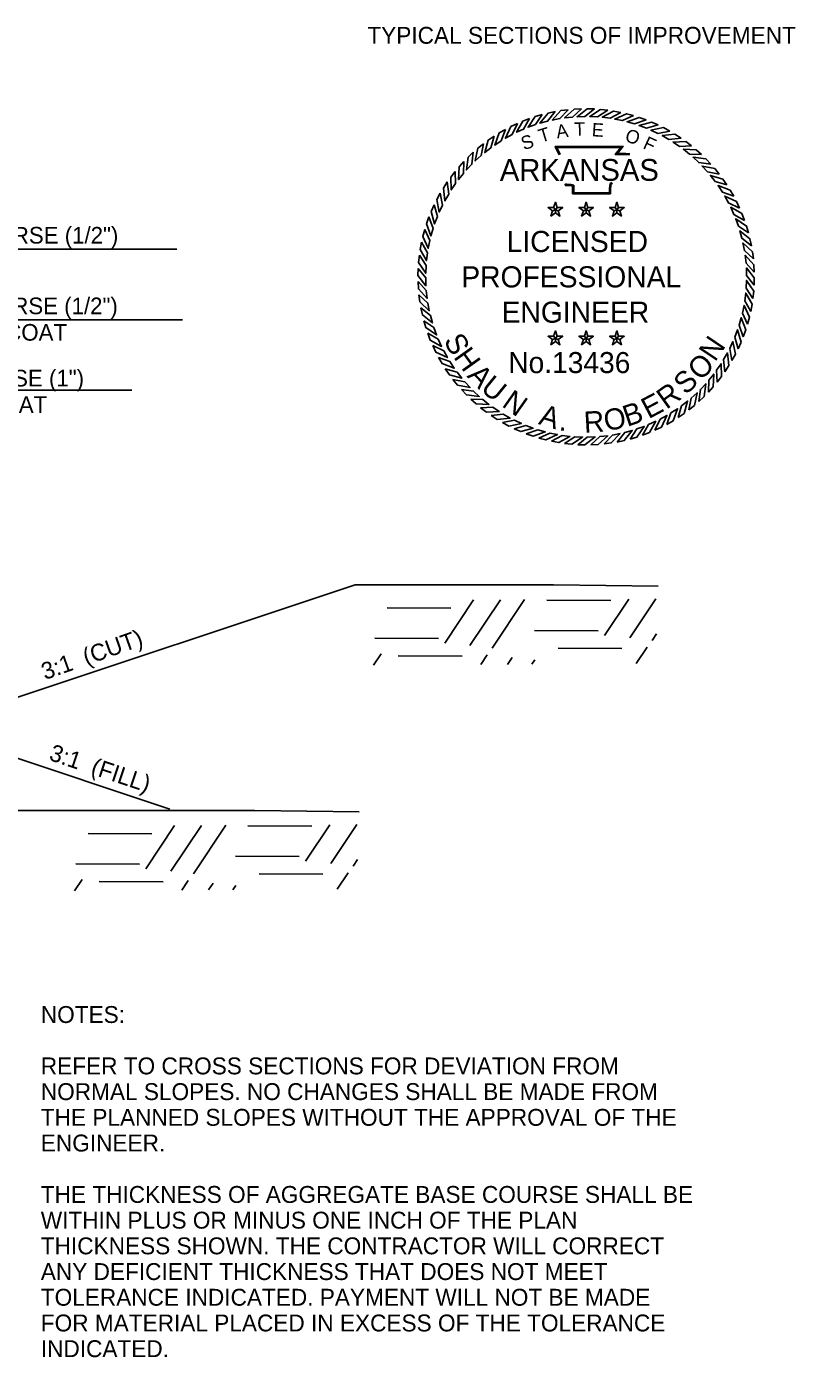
# Model space of a CAD drawing. Extents: x 1398183 to 1398373, y 1967240 to 1968889.
# Drawn here: x 1398309.13 to 1398336.4, y 1967288.58 to 1967335.82 of the extents above; entities that cross this region are included whole.
import ezdxf

# ---------------------------------------------------------------- set-up
doc = ezdxf.new("R2010")
doc.units = 0
for name, color, linetype in [('1', 7, 'Continuous'), ('19', 7, 'Continuous'), ('20', 7, 'Continuous'), ('42', 7, 'Continuous'), ('9', 7, 'Continuous'), ('G-ANNO-SYMB', 7, 'Continuous')]:
    doc.layers.add(name, color=color, linetype=linetype)

msp = doc.modelspace()

# ---------------------------------------------------------------- linework, layer by layer
at = {"layer": '19'}
for q in [(1398320.78, 1967316.011), (1398314.215, 1967308.042)]:
    msp.add_line((1398305.544, 1967310.932), q, dxfattribs=at)
at = {"layer": '20'}
for p, q in [((1398286.544, 1967327.92), (1398314.465, 1967327.92)), ((1398286.544, 1967325.42), (1398314.665, 1967325.42)), ((1398286.544, 1967322.92), (1398312.868, 1967322.92))]:
    msp.add_line(p, q, dxfattribs=at)
at = {"layer": '42'}
for points in [[(1398320.78, 1967316.011), (1398327.818, 1967316.011), (1398331.534, 1967315.96)], [(1398307.157, 1967308.001), (1398317.211, 1967308.001), (1398320.926, 1967307.951)]]:
    msp.add_lwpolyline(points, dxfattribs=at)
at = {"layer": '9'}
for p, q in [((1398324.18, 1967315.183), (1398321.918, 1967315.189)), ((1398324.987, 1967315.473), (1398323.964, 1967313.939)), ((1398325.939, 1967315.478), (1398324.854, 1967313.851)), ((1398326.799, 1967315.483), (1398325.652, 1967313.763)), ((1398329.851, 1967315.456), (1398327.589, 1967315.462)), ((1398330.497, 1967315.504), (1398329.636, 1967314.212)), ((1398331.45, 1967315.509), (1398330.526, 1967314.124)), ((1398323.741, 1967314.105), (1398321.479, 1967314.111)), ((1398329.412, 1967314.378), (1398327.15, 1967314.383)), ((1398331.478, 1967314.266), (1398331.324, 1967314.036)), ((1398330.25, 1967313.752), (1398327.988, 1967313.757)), ((1398331.14, 1967313.794), (1398330.752, 1967313.211)), ((1398321.704, 1967313.555), (1398321.44, 1967313.159)), ((1398324.578, 1967313.479), (1398322.316, 1967313.485)), ((1398325.468, 1967313.521), (1398325.241, 1967313.18)), ((1398326.358, 1967313.433), (1398326.193, 1967313.185)), ((1398327.156, 1967313.345), (1398327.053, 1967313.19)), ((1398319.89, 1967307.494), (1398319.028, 1967306.202)), ((1398320.842, 1967307.5), (1398319.919, 1967306.114)), ((1398313.572, 1967307.173), (1398311.31, 1967307.179)), ((1398314.379, 1967307.463), (1398313.357, 1967305.929)), ((1398315.332, 1967307.469), (1398314.247, 1967305.842)), ((1398316.192, 1967307.474), (1398315.045, 1967305.753)), ((1398319.244, 1967307.446), (1398316.982, 1967307.452)), ((1398313.133, 1967306.095), (1398310.871, 1967306.101)), ((1398318.805, 1967306.368), (1398316.543, 1967306.374)), ((1398320.87, 1967306.257), (1398320.717, 1967306.026)), ((1398319.643, 1967305.742), (1398317.381, 1967305.748)), ((1398320.533, 1967305.784), (1398320.144, 1967305.201)), ((1398311.097, 1967305.546), (1398310.833, 1967305.149)), ((1398313.971, 1967305.469), (1398311.709, 1967305.475)), ((1398314.861, 1967305.511), (1398314.634, 1967305.171)), ((1398315.751, 1967305.423), (1398315.586, 1967305.176)), ((1398316.549, 1967305.335), (1398316.446, 1967305.181))]:
    msp.add_line(p, q, dxfattribs=at)
at = {"layer": 'G-ANNO-SYMB'}
for points in [[(1398326.975, 1967332.56), (1398326.735, 1967332.469), (1398326.51, 1967332.071), (1398326.763, 1967332.185)], [(1398327.422, 1967332.7), (1398327.176, 1967332.628), (1398326.92, 1967332.249), (1398327.181, 1967332.343)], [(1398327.879, 1967332.805), (1398327.628, 1967332.752), (1398327.343, 1967332.394), (1398327.61, 1967332.467)], [(1398328.342, 1967332.873), (1398328.088, 1967332.84), (1398327.776, 1967332.506), (1398328.048, 1967332.558)], [(1398328.81, 1967332.905), (1398328.553, 1967332.892), (1398328.216, 1967332.583), (1398328.492, 1967332.614)], [(1398329.278, 1967332.9), (1398329.021, 1967332.907), (1398328.661, 1967332.626), (1398328.938, 1967332.634)], [(1398329.745, 1967332.858), (1398329.489, 1967332.886), (1398329.108, 1967332.633), (1398329.385, 1967332.62)], [(1398330.206, 1967332.78), (1398329.954, 1967332.827), (1398329.554, 1967332.606), (1398329.829, 1967332.571)], [(1398330.661, 1967332.666), (1398330.413, 1967332.733), (1398329.997, 1967332.543), (1398330.268, 1967332.487)], [(1398331.105, 1967332.516), (1398330.863, 1967332.602), (1398330.433, 1967332.446), (1398330.699, 1967332.369)], [(1398326.121, 1967332.177), (1398325.898, 1967332.05), (1398325.738, 1967331.621), (1398325.97, 1967331.774)], [(1398326.54, 1967332.386), (1398326.309, 1967332.276), (1398326.115, 1967331.861), (1398326.358, 1967331.995)], [(1398331.535, 1967332.332), (1398331.301, 1967332.437), (1398330.861, 1967332.315), (1398331.12, 1967332.217)], [(1398331.951, 1967332.115), (1398331.725, 1967332.238), (1398331.277, 1967332.151), (1398331.527, 1967332.033)], [(1398325.337, 1967331.666), (1398325.137, 1967331.505), (1398325.046, 1967331.057), (1398325.251, 1967331.243)], [(1398325.719, 1967331.937), (1398325.507, 1967331.792), (1398325.381, 1967331.353), (1398325.6, 1967331.523)], [(1398332.347, 1967331.866), (1398332.132, 1967332.006), (1398331.678, 1967331.955), (1398331.919, 1967331.817)], [(1398332.723, 1967331.587), (1398332.52, 1967331.743), (1398332.063, 1967331.727), (1398332.292, 1967331.572)], [(1398324.977, 1967331.365), (1398324.791, 1967331.189), (1398324.735, 1967330.735), (1398324.925, 1967330.937)], [(1398333.076, 1967331.279), (1398332.886, 1967331.451), (1398332.429, 1967331.471), (1398332.646, 1967331.298)], [(1398333.404, 1967330.944), (1398333.228, 1967331.13), (1398332.774, 1967331.186), (1398332.976, 1967330.997)], [(1398324.335, 1967330.685), (1398324.178, 1967330.481), (1398324.194, 1967330.025), (1398324.35, 1967330.254)], [(1398324.643, 1967331.038), (1398324.471, 1967330.847), (1398324.451, 1967330.391), (1398324.624, 1967330.607)], [(1398333.704, 1967330.585), (1398333.543, 1967330.784), (1398333.095, 1967330.875), (1398333.282, 1967330.671)], [(1398324.055, 1967330.309), (1398323.915, 1967330.094), (1398323.967, 1967329.639), (1398324.104, 1967329.88)], [(1398333.976, 1967330.203), (1398333.831, 1967330.414), (1398333.391, 1967330.54), (1398333.561, 1967330.321)], [(1398334.216, 1967329.801), (1398334.088, 1967330.023), (1398333.66, 1967330.183), (1398333.812, 1967329.952)], [(1398323.806, 1967329.912), (1398323.683, 1967329.687), (1398323.771, 1967329.238), (1398323.888, 1967329.489)], [(1398334.424, 1967329.381), (1398334.314, 1967329.613), (1398333.9, 1967329.806), (1398334.034, 1967329.563)], [(1398323.589, 1967329.497), (1398323.484, 1967329.263), (1398323.606, 1967328.822), (1398323.704, 1967329.081)], [(1398327.889, 1967329.317), (1398327.828, 1967329.401), (1398327.63, 1967329.401), (1398327.79, 1967329.285)], [(1398327.889, 1967329.317), (1398327.79, 1967329.285), (1398327.729, 1967329.096), (1398327.889, 1967329.213)], [(1398327.889, 1967329.317), (1398327.95, 1967329.401), (1398327.889, 1967329.59), (1398327.828, 1967329.401)], [(1398327.889, 1967329.317), (1398327.988, 1967329.285), (1398328.148, 1967329.401), (1398327.95, 1967329.401)], [(1398327.889, 1967329.317), (1398327.889, 1967329.213), (1398328.049, 1967329.096), (1398327.988, 1967329.285)], [(1398328.98, 1967329.317), (1398328.919, 1967329.401), (1398328.721, 1967329.401), (1398328.881, 1967329.285)], [(1398328.98, 1967329.317), (1398328.881, 1967329.285), (1398328.82, 1967329.096), (1398328.98, 1967329.213)], [(1398328.98, 1967329.317), (1398329.041, 1967329.401), (1398328.98, 1967329.59), (1398328.919, 1967329.401)], [(1398328.98, 1967329.317), (1398329.079, 1967329.285), (1398329.239, 1967329.401), (1398329.041, 1967329.401)], [(1398328.98, 1967329.317), (1398328.98, 1967329.213), (1398329.14, 1967329.096), (1398329.079, 1967329.285)], [(1398330.071, 1967329.317), (1398330.01, 1967329.401), (1398329.812, 1967329.401), (1398329.972, 1967329.285)], [(1398330.071, 1967329.317), (1398329.972, 1967329.285), (1398329.911, 1967329.096), (1398330.071, 1967329.213)], [(1398330.071, 1967329.317), (1398330.132, 1967329.401), (1398330.071, 1967329.59), (1398330.01, 1967329.401)], [(1398330.071, 1967329.317), (1398330.17, 1967329.285), (1398330.33, 1967329.401), (1398330.132, 1967329.401)], [(1398330.071, 1967329.317), (1398330.071, 1967329.213), (1398330.231, 1967329.096), (1398330.17, 1967329.285)], [(1398334.599, 1967328.946), (1398334.508, 1967329.186), (1398334.11, 1967329.411), (1398334.224, 1967329.159)], [(1398323.405, 1967329.066), (1398323.319, 1967328.824), (1398323.475, 1967328.395), (1398323.553, 1967328.661)], [(1398334.739, 1967328.499), (1398334.667, 1967328.745), (1398334.288, 1967329.001), (1398334.382, 1967328.74)], [(1398323.256, 1967328.622), (1398323.189, 1967328.374), (1398323.378, 1967327.958), (1398323.434, 1967328.23)], [(1398334.843, 1967328.043), (1398334.791, 1967328.294), (1398334.433, 1967328.578), (1398334.506, 1967328.311)], [(1398323.141, 1967328.168), (1398323.094, 1967327.916), (1398323.316, 1967327.516), (1398323.35, 1967327.791)], [(1398334.912, 1967327.579), (1398334.879, 1967327.834), (1398334.544, 1967328.146), (1398334.596, 1967327.873)], [(1398323.063, 1967327.706), (1398323.036, 1967327.451), (1398323.288, 1967327.069), (1398323.301, 1967327.346)], [(1398334.944, 1967327.112), (1398334.931, 1967327.368), (1398334.622, 1967327.705), (1398334.652, 1967327.43)], [(1398323.022, 1967327.239), (1398323.014, 1967326.983), (1398323.296, 1967326.622), (1398323.287, 1967326.9)], [(1398334.939, 1967326.643), (1398334.946, 1967326.9), (1398334.664, 1967327.26), (1398334.673, 1967326.983)], [(1398323.017, 1967326.771), (1398323.029, 1967326.515), (1398323.338, 1967326.177), (1398323.308, 1967326.453)], [(1398334.897, 1967326.177), (1398334.924, 1967326.432), (1398334.672, 1967326.813), (1398334.659, 1967326.536)], [(1398323.048, 1967326.303), (1398323.081, 1967326.049), (1398323.416, 1967325.737), (1398323.364, 1967326.009)], [(1398334.704, 1967325.261), (1398334.771, 1967325.508), (1398334.582, 1967325.924), (1398334.526, 1967325.653)], [(1398334.819, 1967325.715), (1398334.866, 1967325.967), (1398334.644, 1967326.367), (1398334.61, 1967326.092)], [(1398323.117, 1967325.84), (1398323.169, 1967325.589), (1398323.527, 1967325.304), (1398323.454, 1967325.572)], [(1398334.555, 1967324.817), (1398334.641, 1967325.058), (1398334.485, 1967325.488), (1398334.407, 1967325.222)], [(1398323.221, 1967325.383), (1398323.293, 1967325.137), (1398323.672, 1967324.882), (1398323.579, 1967325.142)], [(1398327.889, 1967324.749), (1398327.95, 1967324.833), (1398327.889, 1967325.022), (1398327.828, 1967324.833)], [(1398328.98, 1967324.749), (1398329.041, 1967324.833), (1398328.98, 1967325.022), (1398328.919, 1967324.833)], [(1398330.071, 1967324.749), (1398330.132, 1967324.833), (1398330.071, 1967325.022), (1398330.01, 1967324.833)], [(1398334.371, 1967324.386), (1398334.476, 1967324.62), (1398334.354, 1967325.061), (1398334.256, 1967324.801)], [(1398323.361, 1967324.936), (1398323.452, 1967324.697), (1398323.85, 1967324.471), (1398323.736, 1967324.724)], [(1398323.536, 1967324.502), (1398323.646, 1967324.27), (1398324.06, 1967324.077), (1398323.926, 1967324.319)], [(1398327.889, 1967324.749), (1398327.828, 1967324.833), (1398327.63, 1967324.833), (1398327.79, 1967324.717)], [(1398327.889, 1967324.749), (1398327.79, 1967324.717), (1398327.729, 1967324.528), (1398327.889, 1967324.645)], [(1398327.889, 1967324.749), (1398327.988, 1967324.717), (1398328.148, 1967324.833), (1398327.95, 1967324.833)], [(1398327.889, 1967324.749), (1398327.889, 1967324.645), (1398328.049, 1967324.528), (1398327.988, 1967324.717)], [(1398328.98, 1967324.749), (1398328.919, 1967324.833), (1398328.721, 1967324.833), (1398328.881, 1967324.717)], [(1398328.98, 1967324.749), (1398328.881, 1967324.717), (1398328.82, 1967324.528), (1398328.98, 1967324.645)], [(1398328.98, 1967324.749), (1398329.079, 1967324.717), (1398329.239, 1967324.833), (1398329.041, 1967324.833)], [(1398328.98, 1967324.749), (1398328.98, 1967324.645), (1398329.14, 1967324.528), (1398329.079, 1967324.717)], [(1398330.071, 1967324.749), (1398330.01, 1967324.833), (1398329.812, 1967324.833), (1398329.972, 1967324.717)], [(1398330.071, 1967324.749), (1398329.972, 1967324.717), (1398329.911, 1967324.528), (1398330.071, 1967324.645)], [(1398330.071, 1967324.749), (1398330.17, 1967324.717), (1398330.33, 1967324.833), (1398330.132, 1967324.833)], [(1398330.071, 1967324.749), (1398330.071, 1967324.645), (1398330.231, 1967324.528), (1398330.17, 1967324.717)], [(1398334.154, 1967323.971), (1398334.277, 1967324.196), (1398334.19, 1967324.645), (1398334.072, 1967324.394)], [(1398323.744, 1967324.082), (1398323.872, 1967323.86), (1398324.3, 1967323.699), (1398324.148, 1967323.931)], [(1398333.905, 1967323.574), (1398334.045, 1967323.789), (1398333.993, 1967324.243), (1398333.856, 1967324.002)], [(1398323.984, 1967323.68), (1398324.129, 1967323.468), (1398324.569, 1967323.342), (1398324.399, 1967323.561)], [(1398333.625, 1967323.198), (1398333.782, 1967323.401), (1398333.766, 1967323.858), (1398333.61, 1967323.629)], [(1398324.256, 1967323.298), (1398324.417, 1967323.098), (1398324.865, 1967323.007), (1398324.678, 1967323.212)], [(1398332.983, 1967322.517), (1398333.169, 1967322.694), (1398333.225, 1967323.147), (1398333.035, 1967322.945)], [(1398333.317, 1967322.845), (1398333.49, 1967323.035), (1398333.509, 1967323.492), (1398333.336, 1967323.276)], [(1398324.556, 1967322.939), (1398324.732, 1967322.752), (1398325.186, 1967322.696), (1398324.984, 1967322.886)], [(1398324.884, 1967322.604), (1398325.074, 1967322.432), (1398325.531, 1967322.412), (1398325.314, 1967322.585)], [(1398332.623, 1967322.217), (1398332.823, 1967322.378), (1398332.914, 1967322.826), (1398332.709, 1967322.639)], [(1398325.237, 1967322.296), (1398325.44, 1967322.139), (1398325.897, 1967322.155), (1398325.668, 1967322.311)], [(1398331.839, 1967321.705), (1398332.062, 1967321.833), (1398332.222, 1967322.261), (1398331.99, 1967322.109)], [(1398332.241, 1967321.946), (1398332.453, 1967322.091), (1398332.579, 1967322.53), (1398332.36, 1967322.36)], [(1398325.613, 1967322.017), (1398325.828, 1967321.876), (1398326.282, 1967321.928), (1398326.041, 1967322.065)], [(1398326.009, 1967321.768), (1398326.235, 1967321.645), (1398326.684, 1967321.732), (1398326.433, 1967321.85)], [(1398326.425, 1967321.55), (1398326.659, 1967321.446), (1398327.099, 1967321.568), (1398326.84, 1967321.666)], [(1398330.985, 1967321.322), (1398331.225, 1967321.414), (1398331.45, 1967321.812), (1398331.197, 1967321.698)], [(1398331.42, 1967321.497), (1398331.651, 1967321.607), (1398331.845, 1967322.021), (1398331.602, 1967321.888)], [(1398326.855, 1967321.367), (1398327.097, 1967321.28), (1398327.527, 1967321.437), (1398327.261, 1967321.514)], [(1398327.299, 1967321.217), (1398327.547, 1967321.15), (1398327.963, 1967321.34), (1398327.692, 1967321.396)], [(1398327.754, 1967321.103), (1398328.006, 1967321.055), (1398328.406, 1967321.277), (1398328.131, 1967321.312)], [(1398328.216, 1967321.025), (1398328.471, 1967320.997), (1398328.852, 1967321.25), (1398328.575, 1967321.263)], [(1398328.682, 1967320.983), (1398328.939, 1967320.976), (1398329.299, 1967321.257), (1398329.022, 1967321.248)], [(1398329.151, 1967320.978), (1398329.407, 1967320.991), (1398329.744, 1967321.3), (1398329.468, 1967321.269)], [(1398329.618, 1967321.01), (1398329.872, 1967321.043), (1398330.184, 1967321.377), (1398329.912, 1967321.325)], [(1398330.081, 1967321.078), (1398330.332, 1967321.131), (1398330.617, 1967321.489), (1398330.35, 1967321.415)], [(1398330.538, 1967321.182), (1398330.784, 1967321.255), (1398331.04, 1967321.634), (1398330.779, 1967321.54)]]:
    msp.add_lwpolyline(points, close=True, dxfattribs=at)
for points in [[(1398328.024, 1967331.271), (1398327.885, 1967331.573), (1398330.292, 1967331.574), (1398330.09, 1967331.321), (1398330.254, 1967331.323), (1398330.391, 1967331.325), (1398330.527, 1967331.31)], [(1398328.059, 1967331.287), (1398327.945, 1967331.534), (1398330.212, 1967331.536), (1398330.011, 1967331.282), (1398330.254, 1967331.285), (1398330.389, 1967331.287), (1398330.523, 1967331.272)], [(1398329.912, 1967330.263), (1398329.871, 1967330.23), (1398329.858, 1967330.18), (1398329.844, 1967330.055), (1398329.844, 1967329.889), (1398328.501, 1967329.889), (1398328.501, 1967330.113), (1398328.501, 1967330.163), (1398328.446, 1967330.18), (1398328.255, 1967330.18), (1398328.221, 1967330.231)], [(1398329.888, 1967330.292), (1398329.838, 1967330.251), (1398329.82, 1967330.187), (1398329.806, 1967330.057), (1398329.806, 1967329.927), (1398328.539, 1967329.927), (1398328.539, 1967330.113), (1398328.539, 1967330.191), (1398328.452, 1967330.218), (1398328.276, 1967330.218), (1398328.253, 1967330.252)]]:
    msp.add_lwpolyline(points, dxfattribs=at)

# ---------------------------------------------------------------- texts
at = {"layer": '1'}
msp.add_text('TYPICAL SECTIONS OF IMPROVEMENT', height=0.6, dxfattribs=at).set_placement((1398321.219, 1967335.214))
at = {"layer": '19'}
for s, p in [('NOTES:', (1398309.634, 1967300.455)), ('REFER TO CROSS SECTIONS FOR DEVIATION FROM', (1398309.634, 1967298.63)), ('NORMAL SLOPES. NO CHANGES SHALL BE MADE FROM ', (1398309.634, 1967297.718)), ('THE PLANNED SLOPES WITHOUT THE APPROVAL OF THE', (1398309.634, 1967296.805)), ('ENGINEER.', (1398309.634, 1967295.893)), ('THE THICKNESS OF AGGREGATE BASE COURSE SHALL BE', (1398309.634, 1967294.068)), ('WITHIN PLUS OR MINUS ONE INCH OF THE PLAN ', (1398309.634, 1967293.155)), ('THICKNESS SHOWN. THE CONTRACTOR WILL CORRECT', (1398309.634, 1967292.243)), ('ANY DEFICIENT THICKNESS THAT DOES NOT MEET', (1398309.634, 1967291.33)), ('TOLERANCE INDICATED. PAYMENT WILL NOT BE MADE', (1398309.634, 1967290.418)), ('FOR MATERIAL PLACED IN EXCESS OF THE TOLERANCE', (1398309.634, 1967289.505)), ('INDICATED.', (1398309.634, 1967288.593))]:
    msp.add_text(s, height=0.6, dxfattribs=at).set_placement(p)
at = {"layer": '42'}
for s, height, rotation, p in [('VAR. ACHM SURFACE COURSE (1/2")', 0.59001, 360, (1398298.295, 1967328.123)), ('VAR. ACHM SURFACE COURSE (1/2")', 0.59001, 360, (1398298.276, 1967325.616)), ('(220 LB/SQ.YD) & TACK COAT', 0.59001, 360, (1398299.384, 1967324.676)), ('VAR. ACHM BINDER COURSE (1")', 0.59001, 360, (1398298.525, 1967323.05)), ('(495 LB/SQ.YD) & TACK COAT', 0.59001, 360, (1398298.681, 1967322.11)), ('3:1  (CUT)', 0.6, 19.5057, (1398309.78, 1967312.625)), ('3:1  (FILL)', 0.6, 341.5651, (1398309.892, 1967309.799))]:
    msp.add_text(s, height=height, rotation=rotation, dxfattribs=at).set_placement(p)
at = {"layer": 'G-ANNO-SYMB'}
for s, height, rotation, p in [('T', 0.475, 16.9015, (1398327.375, 1967331.7)), ('A', 0.475, 8.6788, (1398327.951, 1967331.851)), ('T', 0.475, 1.4789, (1398328.564, 1967331.945)), ('E', 0.475, 356.672, (1398329.171, 1967331.931)), ('O', 0.475, 341.2218, (1398330.324, 1967331.768)), ('S', 0.475, 19.7726, (1398326.771, 1967331.429)), ('F', 0.475, 335.3628, (1398330.964, 1967331.518)), ('S', 0.75, 298.1636, (1398323.912, 1967324.682)), ('N', 0.75, 56.1007, (1398333.554, 1967323.898)), ('H', 0.75, 305.619, (1398324.254, 1967324.094)), ('O', 0.75, 44.7757, (1398333.033, 1967323.223)), ('A', 0.75, 313.4472, (1398324.73, 1967323.409)), ('S', 0.75, 43.4878, (1398332.518, 1967322.725)), ('U', 0.75, 320.9026, (1398325.198, 1967322.92)), ('R', 0.75, 35.6597, (1398331.828, 1967322.215)), ('N', 0.75, 324.9326, (1398325.954, 1967322.362)), ('E', 0.75, 27.8315, (1398331.194, 1967321.883)), ('A', 0.75, 343.0991, (1398327.261, 1967321.718)), ('R', 0.75, 3.2287, (1398328.918, 1967321.405)), ('O', 0.75, 11.4296, (1398329.685, 1967321.453)), ('B', 0.75, 18.885, (1398330.437, 1967321.612)), ('.', 0.75, 351.3, (1398327.998, 1967321.5))]:
    msp.add_text(s, height=height, rotation=rotation, dxfattribs=at).set_placement(p)
for s, height, p in [('ARKANSAS', 0.7747, (1398325.918, 1967330.349)), ('LICENSED', 0.75, (1398326.159, 1967327.821)), ('PROFESSIONAL', 0.75, (1398324.551, 1967326.566)), ('ENGINEER', 0.75, (1398325.98, 1967325.312)), ('No.13436', 0.747, (1398326.217, 1967323.524))]:
    msp.add_text(s, height=height, dxfattribs=at).set_placement(p)

doc.saveas('drawing.dxf')
